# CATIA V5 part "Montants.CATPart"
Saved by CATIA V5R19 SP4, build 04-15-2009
Part number: Montants
Bounding box of the stored display mesh (mm): x -591 to 439, y 85 to 1350, z -200 to 1830
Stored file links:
  G:\EU_thinkMotion\CFAO_2010\MMS_groupe1\MMS_groupe1\OK\rragonneau\rragonneau\Montants.CATPart
  D:\Documents\Scolaire\MM2\CFAO\Brevet\MODELE CATIA\Squelette\Deambulateur.CATProduct
  G:\EU_thinkMotion\CFAO_2010\MMS_groupe1\MMS_groupe1\OK\rragonneau\rragonneau\Squelette bati.CATPart
  G:\EU_thinkMotion\CFAO_2010\MMS_groupe1\MMS_groupe1\OK\rragonneau\rragonneau\Bras 1.CATPart
  G:\EU_thinkMotion\CFAO_2010\MMS_groupe1\MMS_groupe1\OK\rragonneau\rragonneau\Bras 2.CATPart
  G:\EU_thinkMotion\CFAO_2010\MMS_groupe1\MMS_groupe1\OK\rragonneau\rragonneau\Pneus.CATPart
  G:\EU_thinkMotion\CFAO_2010\MMS_groupe1\MMS_groupe1\OK\rragonneau\rragonneau\squelette de base.CATPart
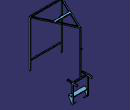
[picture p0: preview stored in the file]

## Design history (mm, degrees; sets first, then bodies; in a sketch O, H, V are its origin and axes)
External parameters (linked from other documents)
  `External.diam_moyeu_ext / epaisseur_bras&montant` = 60 mm
  External.largeur_siege = 500 mm
  External.profondeur_treuil = 500 mm
  External.diam_roue = 200 mm
Set1
  Sketch1 on Plane1, origin (0, 100, 0), H (-1, 0, 0), V (0, 0, 1)
    line L1 (-439, 1800) -> (-409, 1800)
    line L2 (-409, 1800) -> (-409, 335.4102)
    line L3 (-409, 335.4102) -> (-439, 335.4102)
    line L4 (-439, 335.4102) -> (-439, 1800)
    reference projected line E1 (-424, 793.7254) -> (-424, 2500) from Line1
    reference projected line E2 (-424, 793.7254) -> (-424, 2500) from Line1
    reference intersected line E3 through (0, 1800) direction (-1, 0) from Plane2
    reference intersected line E4 through (0, 335.4102) direction (-1, 0) from Plane3
    distance E1 L2 = 15 {= `External.diam_moyeu_ext / epaisseur_bras&montant` /4}
    distance L4 E2 = 15 {= `External.diam_moyeu_ext / epaisseur_bras&montant` /4}
    horizontal: L1 H, L3 H
    vertical: L2 V, L4 V
    coincidence: L1 E3, L3 E4
  Sketch2 on Plane1, origin (0, 100, 0), H (-1, 0, 0), V (0, 0, 1)
    line L1 (561, 1800) -> (591, 1800)
    line L2 (591, 1800) -> (591, 335.4102)
    line L3 (591, 335.4102) -> (561, 335.4102)
    line L4 (561, 335.4102) -> (561, 1800)
    reference intersected line E1 through (0, 1800) direction (-1, 0) from Plane2
    reference intersected line E2 through (0, 335.4102) direction (-1, 0) from Plane4
    reference projected line E3 (576, 793.7254) -> (576, 2500) from Line2
    reference projected line E4 (576, 793.7254) -> (576, 2500) from Line2
    distance E3 L2 = 15 {= `External.diam_moyeu_ext / epaisseur_bras&montant` /4}
    distance L4 E4 = 15 {= `External.diam_moyeu_ext / epaisseur_bras&montant` /4}
    horizontal: L1 H, L3 H
    vertical: L2 V, L4 V
    coincidence: L1 E1, L3 E2
  Sketch3 on Plane5, origin (0, 1200, 0), H (-1, 0, 0), V (0, 0, 1)
    line L1 (61, 1800) -> (91, 1800)
    line L2 (91, 1800) -> (91, 415)
    line L3 (91, 415) -> (61, 415)
    line L4 (61, 415) -> (61, 1800)
    reference intersected line E1 through (0, 1800) direction (-1, 0) from Plane2
    reference intersected line E2 through (0, 415) direction (-1, 0) from Plane6
    reference projected line E3 (76, 2500) -> (76, 400) from Line3
    reference projected line E4 (76, 2500) -> (76, 400) from Line3
    distance L2 E3 = 15 {= `External.diam_moyeu_ext / epaisseur_bras&montant` /4}
    distance L4 E4 = 15 {= `External.diam_moyeu_ext / epaisseur_bras&montant` /4}
    horizontal: L1 H, L3 H
    vertical: L2 V, L4 V
    coincidence: L1 E1, L3 E2
Set2
  Plane1: linked copy from another document
  Line1: linked copy from another document
  Plane2 to Plane4: linked copy from another document
  Line2: linked copy from another document
  Plane5: linked copy from another document
  Plane6: linked copy from another document
  Line3: linked copy from another document
  Point1: linked copy from another document
  Point2: linked copy from another document
  Plane7: linked copy from another document
  Point3 to Point6: linked copy from another document
  Plane8 to Plane11: linked copy from another document
  Point7: linked copy from another document
  Point8: linked copy from another document
Body1 (main body)
  Pad1: profile Sketch1, direction (0, 1, 0), length 15 {= `External.diam_moyeu_ext / epaisseur_bras&montant` /4}, opposite side length 15 {= `External.diam_moyeu_ext / epaisseur_bras&montant` /4}
  Pad2: profile Sketch2, direction (0, 1, 0), length 15 {= `External.diam_moyeu_ext / epaisseur_bras&montant` /4}, opposite side length 15 {= `External.diam_moyeu_ext / epaisseur_bras&montant` /4}
  Pad3: profile Sketch3, direction (0, 1, 0), length 15 {= `External.diam_moyeu_ext / epaisseur_bras&montant` /4}, opposite side length 15 {= `External.diam_moyeu_ext / epaisseur_bras&montant` /4}
  Sketch4 on Plane7, origin (0, 0, 400), H (1, 0, 0), V (0, 1, 0)
    line L1 (-326, 1215) -> (-326, 1035)
    point P2 (-326, 1035)
    line L2 (-326, 1035) -> (-296, 1035)
    point P3 (-326, 1035)
    line L3 (-296, 1035) -> (-296, 1185)
    line L4 (-296, 1185) -> (144, 1185)
    line L5 (144, 1185) -> (144, 1035)
    point P7 (144, 1035)
    line L6 (144, 1035) -> (174, 1035)
    line L7 (174, 1035) -> (174, 1215)
    line L8 (174, 1215) -> (-326, 1215)
    reference projected point E1 (-76, 1200) from Line3
    reference projected point E2 (-326, 1200) from Point2
    reference projected point E3 (174, 1200) from Point1
    reference projected point E4 (174, 1200) from Point1
    distance L8 L4 = 30 {= `External.diam_moyeu_ext / epaisseur_bras&montant` /2}
    distance L8 E1 = 15 {= `External.diam_moyeu_ext / epaisseur_bras&montant` /4}
    length L6 = 30 {= `External.diam_moyeu_ext / epaisseur_bras&montant` /2}
    length L2 = 30 {= `External.diam_moyeu_ext / epaisseur_bras&montant` /2}
    distance L6 E4 = 165 {= 150mm+`External.diam_moyeu_ext / epaisseur_bras&montant` /4}
    vertical: L1 V, L3 V, L5 V, L7 V
    horizontal: L2 H, L4 H, L6 H, L8 H
    coincidence: P7 L2, P2 P3, L1 E2, L7 E3
  Sketch5 on Plane7, origin (0, 0, 400), H (1, 0, 0), V (0, 1, 0)
    line L1 (144, 1350) -> (174, 1350)
    line L2 (174, 1350) -> (174, 1200)
    line L3 (174, 1200) -> (144, 1200)
    line L4 (144, 1200) -> (144, 1350)
    point P3 (174, 1200)
    reference projected line E1 (174, 1865) -> (174, 2015) from Sketch4.L7
    reference projected point E2 (174, 1200) from Point1
    reference projected line E3 (144, 1985) -> (144, 1865) from Sketch4.L5
    line L5 (-326, 1350) -> (-296, 1350)
    line L6 (-296, 1350) -> (-296, 1200)
    line L7 (-296, 1200) -> (-326, 1200)
    line L8 (-326, 1200) -> (-326, 1350)
    reference projected line E4 (-326, 2015) -> (-326, 1865) from Sketch4.L1
    reference projected line E5 (-296, 1865) -> (-296, 1985) from Sketch4.L3
    reference projected point E6 (-326, 1200) from Point2
    length L2 = 150
    length L8 = 150
    horizontal: L1 H, L3 H, L5 H, L7 H
    vertical: L2 V, L4 V, L6 V, L8 V
    coincidence: L2 E1, P3 E2, L4 E3, L8 E4, L6 E5, L7 E6
  Pad4: profile Sketch4, direction (0, 0, 1), length 15 {= `External.diam_moyeu_ext / epaisseur_bras&montant` /4}, opposite side length 15 {= `External.diam_moyeu_ext / epaisseur_bras&montant` /4}
  Pad5: profile Sketch5, direction (0, 0, 1), length 15 {= `External.diam_moyeu_ext / epaisseur_bras&montant` /4}, opposite side length 30 {= `External.diam_moyeu_ext / epaisseur_bras&montant` /2}
  Sketch6 on face of Pad4 from Sketch4.L3, origin (-296, 0, 0), H (0, 1, 0), V (0, 0, 1)
    circle A1 centre (1050, 400) radius 10
    point P1 (1050, 400)
    reference intersected line E1 through (0, 400) direction (-1, 0) from Plane7
    reference projected point E2 (1050, 400) from Point3
    radius A1 = 10 {= `External.diam_moyeu_ext / epaisseur_bras&montant` /6}
    coincidence: P1 E1, E2 P1
  Pad6: profile Sketch6, direction (1, 0, 0), length 20
  Sketch7 on face of Pad4 from Sketch4.L5, origin (144, 0, 0), H (0, -1, 0), V (0, 0, 1)
    circle A1 centre (-1050, 400) radius 7.5
    point P1 (-1050, 400)
    reference intersected line E1 through (0, 400) direction (-1, 0) from Plane7
    reference projected point E2 (-1050, 400) from Point4
    radius A1 = 7.5 {= `External.diam_moyeu_ext / epaisseur_bras&montant` /8}
    coincidence: P1 E1, P1 E2
  Pad7: profile Sketch7, direction (-1, 0, 0), length 20
  Sketch8 on Plane5, origin (0, 1200, 0), H (-1, 0, 0), V (0, 0, 1)
    line L1 (-174, 415) -> (-144, 415)
    line L2 (-144, 415) -> (-144, 0)
    line L3 (-144, 0) -> (-174, 0)
    line L4 (-174, 0) -> (-174, 415)
    reference projected point E1 (-174, 0) from Point5
    reference intersected line E2 (-174, 385) -> (-174, 415) from face of Pad5
    reference intersected line E3 (-424, 415) -> (576, 415) from face of Pad5
    length L3 = 30 {= `External.diam_moyeu_ext / epaisseur_bras&montant` /2}
    horizontal: L1 H, L3 H
    vertical: L2 V, L4 V
    coincidence: L3 E1, L4 E2, E3 L1
  Sketch9 on Plane5, origin (0, 1200, 0), H (-1, 0, 0), V (0, 0, 1)
    line L1 (296, 415) -> (326, 415)
    line L2 (326, 415) -> (326, 0)
    line L3 (326, 0) -> (296, 0)
    line L4 (296, 0) -> (296, 415)
    reference intersected line E1 (326, 415) -> (326, 385) from face of Pad5
    reference intersected line E2 (-424, 415) -> (576, 415) from face of Pad5
    length L3 = 30 {= `External.diam_moyeu_ext / epaisseur_bras&montant` /2}
    horizontal: L1 H
    vertical: L2 V, L4 V
    coincidence: E1 L2, L1 E2
  Sketch10 on Plane5, origin (0, 1200, 0), H (-1, 0, 0), V (0, 0, 1)
    line L1 (-174, 15) -> (326, 15)
    line L2 (326, 15) -> (326, 0)
    line L3 (326, 0) -> (-174, 0)
    line L4 (-174, 0) -> (-174, 15)
    reference projected line E1 (326, 0) -> (326, 415) from Sketch9.L2
    reference projected line E2 (-174, 415) -> (-174, 0) from Sketch8.L4
    reference projected point E3 (326, 0) from Point6
    length L2 = 15 {= `External.diam_moyeu_ext / epaisseur_bras&montant` /4}
    horizontal: L1 H, L3 H
    vertical: L2 V, L4 V
    coincidence: L2 E1, L4 E2, L3 E3
  Pad8: profile Sketch8, direction (0, 1, 0), length 15 {= `External.diam_moyeu_ext / epaisseur_bras&montant` /4}, opposite side length 15 {= `External.diam_moyeu_ext / epaisseur_bras&montant` /4}
  Pad9: profile Sketch9, direction (0, 1, 0), length 15 {= `External.diam_moyeu_ext / epaisseur_bras&montant` /4}, opposite side length 15 {= `External.diam_moyeu_ext / epaisseur_bras&montant` /4}
  Pad10: profile Sketch10, direction (0, 1, 0), length 15 {= `External.diam_moyeu_ext / epaisseur_bras&montant` /4}, opposite side length 120 {= `External.diam_moyeu_ext / epaisseur_bras&montant` *2}
  Sketch11 on Plane5, origin (0, 1200, 0), H (-1, 0, 0), V (0, 0, 1)
    circle A1 centre (76, 1255) radius 7.5
    point P1 (76, 1255)
    reference projected line E1 (76, 2000) -> (76, 415) from Line3
    reference intersected line E2 through (0, 415) direction (-1, 0) from Plane6
    distance E2 P1 = 840
    radius A1 = 7.5 {= `External.diam_moyeu_ext / epaisseur_bras&montant` /8}
    coincidence: E1 P1
  Pad11: profile Sketch11, direction (0, 1, 0), length 80
  Sketch12 on Plane2, origin (0, 0, 1800), H (1, 0, 0), V (0, 1, 0)
    line L1 (-91, 1185) -> (-591, 115)
    point P1 (-91, 1185)
    point P2 (-591, 115)
    line L2 (-591, 115) -> (-591, 85)
    point P3 (-591, 85)
    line L3 (-591, 85) -> (439, 85)
    line L4 (439, 85) -> (439, 115)
    point P5 (439, 115)
    line L5 (439, 115) -> (-61, 1185)
    point P6 (-61, 1185)
    line L6 (-61, 1185) -> (-61, 1215)
    point P7 (-61, 1185)
    line L7 (-91, 1185) -> (-91, 1215)
    line L8 (-91, 1215) -> (-61, 1215)
    reference projected line E1 (-91, 1215) -> (-61, 1215) from edge [face of Pad3 from Sketch3.L1 | end face of Pad3]
    reference projected point E2 (-61, 1185) from vertex [face of Pad3 from Sketch3.L1 | start face of Pad3 | face of Pad3 from Sketch3.L4]
    reference projected point E3 (-91, 1185) from vertex [start face of Pad3 | face of Pad3 from Sketch3.L2 | face of Pad3 from Sketch3.L1]
    reference projected line E4 (659, 85) -> (689, 85) from edge [start face of Pad1 | face of Pad1 from Sketch1.L1]
    reference projected point E5 (439, 115) from vertex [face of Pad1 from Sketch1.L1 | end face of Pad1 | face of Pad1 from Sketch1.L4]
    reference projected point E6 (-591, 85) from vertex [start face of Pad2 | face of Pad2 from Sketch2.L2 | face of Pad2 from Sketch2.L1]
    reference intersected line E7 (-841, 115) -> (-811, 115) from end face of Pad2
    line L9 (-557.8862, 115) -> (405.8862, 115)
    line L10 (405.8862, 115) -> (-76, 1146.2365)
    line L11 (-76, 1146.2365) -> (-557.8862, 115)
    reference intersected line E8 through (0, 100) direction (-1, 0) from Plane1
    distance L9 L3 = 30 {= `External.diam_moyeu_ext / epaisseur_bras&montant` /2}
    distance L11 L1 = 30 {= `External.diam_moyeu_ext / epaisseur_bras&montant` /2}
    distance L10 L5 = 30 {= `External.diam_moyeu_ext / epaisseur_bras&montant` /2}
    vertical: L2 V, L4 V, L6 V, L7 V
    horizontal: L3 H, L8 H, L9 H
    coincidence: P7 L5, P6 P7, L8 E1, P6 E2, P1 E3, L3 E4, P5 E5, P3 E6, P2 E7
    parallelism: E8 L9
  Pad12: profile Sketch12, direction (0, 0, 1), length 30 {= `External.diam_moyeu_ext / epaisseur_bras&montant` /2}
  Sketch13 on Plane2, origin (0, 0, 1800), H (1, 0, 0), V (0, 1, 0)
    line L1 (-303.2133, 660) -> (-331.2507, 600)
    point P2 (-331.2507, 600)
    line L2 (-331.2507, 600) -> (-91, 600)
    point P3 (-331.2507, 600)
    line L3 (-91, 600) -> (-91, 570)
    line L4 (-91, 570) -> (-61, 570)
    line L5 (-303.2133, 660) -> (151.2133, 660)
    line L6 (151.2133, 660) -> (179.2507, 600)
    point P8 (179.2507, 600)
    line L7 (179.2507, 600) -> (-61, 600)
    point P9 (179.2507, 600)
    line L8 (-61, 600) -> (-61, 570)
    reference intersected line E1 (42.7989, 1400.466) -> (-601.4839, 21.701) from face of Pad12 from Sketch12.L11
    reference intersected line E2 (449.4839, 21.701) -> (-194.7989, 1400.466) from face of Pad12 from Sketch12.L10
    axis line L9 (-76, 961.6063) -> (-76, 420.4036)
    reference intersected line E3 through (-76, 0) direction (0, 1) from Plane10
    reference projected point E4 (424, 100) from Line1
    distance L2 L5 = 60 {= `External.diam_moyeu_ext / epaisseur_bras&montant`}
    length L8 = 30 {= `External.diam_moyeu_ext / epaisseur_bras&montant` /2}
    length L4 = 30 {= `External.diam_moyeu_ext / epaisseur_bras&montant` /2}
    distance L8 L9 = 15 {= `External.diam_moyeu_ext / epaisseur_bras&montant` /4}
    distance L7 E4 = 500 {= External.profondeur_treuil}
    horizontal: L2 H, L4 H, L5 H, L7 H
    vertical: L3 V, L8 V, L9 V
    coincidence: P8 L2, P9 L6, L1 E1, L6 E2, P2 P3, L2 L7, L9 E3, P8 P9
  Pad13: profile Sketch13, direction (0, 0, 1), length 30 {= `External.diam_moyeu_ext / epaisseur_bras&montant` /2}
  Sketch14 on Plane11, origin (174, 0, 0), H (0, 1, 0), V (0, 0, 1)
    line L1 (1080, 0) -> (1182.4046, -189.508)
    point P1 (1080, 0)
    line L2 (1215, 0) -> (1080, 0)
    point P2 (1215, 0)
    line L3 (1215, 0) -> (1219.9923, -179.4438)
    reference projected point E1 (1080, 0) from vertex [face of Pad10 from Sketch10.L3 | face of Pad10 from Sketch10.L2 | start face of Pad10]
    reference projected point E2 (1215, 0) from edge [face of Pad10 | face of Pad10]
    arc A1 centre (1200, -180) radius 20 from (1182.4046, -189.508) to (1219.9923, -179.4438) ccw
    point P5 (1200, -180)
    reference projected point E3 (1200, -180) from Point7
    radius A1 = 20
    horizontal: L2 H
    coincidence: P1 E1, P2 E2, E3 P5
    tangency: A1 L1, A1 L3
  Pad14: profile Sketch14, direction (-1, 0, 0), length 30 {= `External.diam_moyeu_ext / epaisseur_bras&montant` /2}
  Sketch15 on Plane11, origin (174, 0, 0), H (0, 1, 0), V (0, 0, 1)
    circle A1 centre (1200, -180) radius 10
    reference projected point E1 (1200, -180) from Point7
    radius A1 = 10
    concentricity: A1 E1
  Pad15: profile Sketch15, direction (-1, 0, 0), length 130 {= `External.diam_moyeu_ext / epaisseur_bras&montant` /2+External.diam_roue /2}
  Mirror1: of Pad14, Pad15, about Plane10
  Sketch16 on Plane1, origin (0, 100, 0), H (-1, 0, 0), V (0, 0, 1)
    line L1 (576, 635) -> (-424, 635)
    line L2 (-424, 635) -> (-424, 605)
    line L3 (-424, 605) -> (576, 605)
    line L4 (576, 605) -> (576, 635)
    reference projected line E1 (-424, 335.4102) -> (-424, 1800) from Line1
    reference projected point E2 (-424, 620) from Point8
    reference projected line E3 (576, 335.4102) -> (576, 1800) from Line2
    distance L1 E2 = 15 {= `External.diam_moyeu_ext / epaisseur_bras&montant` /4}
    distance L3 L1 = 30 {= `External.diam_moyeu_ext / epaisseur_bras&montant` /2}
    horizontal: L1 H, L3 H
    vertical: L2 V, L4 V
    coincidence: L2 E1, L4 E3
  Pad16: profile Sketch16, direction (0, 1, 0), length 15 {= `External.diam_moyeu_ext / epaisseur_bras&montant` /4}, opposite side length 15 {= `External.diam_moyeu_ext / epaisseur_bras&montant` /4}
  Fillet1: radius 15 {= `External.diam_moyeu_ext / epaisseur_bras&montant` /4}, on edge [face of Pad16 | face of Pad16 from Sketch16.L1]
  Fillet2: radius 15 {= `External.diam_moyeu_ext / epaisseur_bras&montant` /4}, on edge [face of Pad16 from Sketch16.L1 | face of Pad16]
